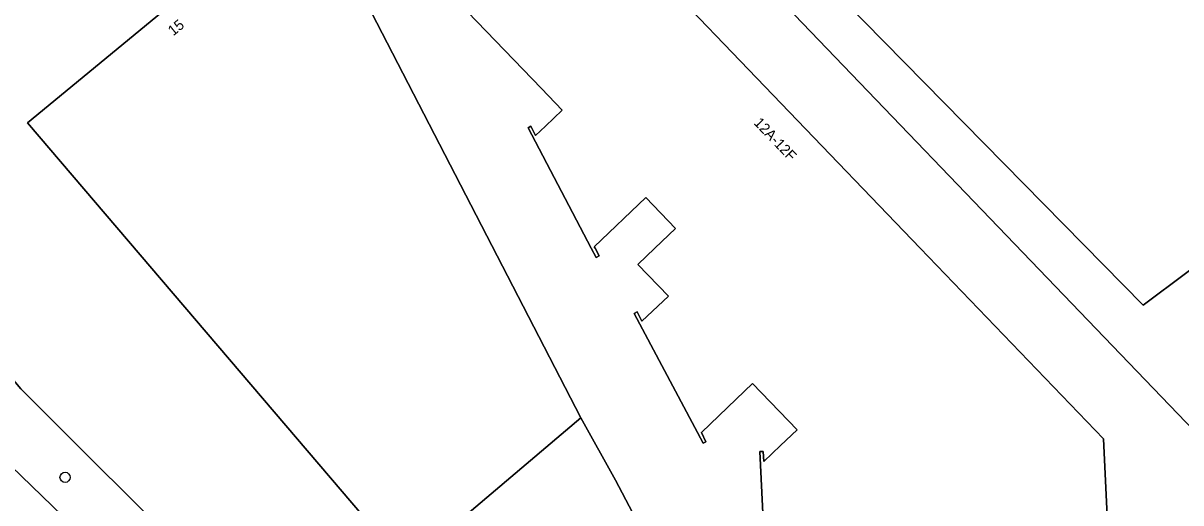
# Model space of a CAD drawing. Extents: x 156141 to 158132, y 385651 to 388333.
# Drawn here: x 156991.8 to 157103, y 387225.5 to 387271.6 of the extents above; entities that cross this region are included whole.
import ezdxf

# ---------------------------------------------------------------- set-up
doc = ezdxf.new("R2010")
doc.units = 0
for name, color, linetype in [('IMGEO_Boom', 7, 'Continuous'), ('IMGEO_Erf', 7, 'Continuous'), ('IMGEO_Groenvoorziening', 7, 'Continuous'), ('IMGEO_Hek', 7, 'Continuous'), ('IMGEO_Pand', 7, 'Continuous'), ('IMGEO_Pand_nummerreeks', 7, 'Continuous'), ('IMGEO_Rijbaan_lokaal_gesloten', 7, 'Continuous')]:
    doc.layers.add(name, color=color, linetype=linetype)

msp = doc.modelspace()

# ---------------------------------------------------------------- linework, layer by layer
at = {"layer": 'IMGEO_Boom'}
msp.add_circle((156995.85, 387227.99), 0.489, dxfattribs=at)
at = {"layer": 'IMGEO_Erf'}
msp.add_lwpolyline([(157102.2, 387360.43), (157098.81, 387358.08), (157089.23, 387351.22), (157088.07, 387350.39), (157077.06, 387342.51), (157051.09, 387323.03), (157046.61, 387319.67), (157039.23, 387314.13), (157031.44, 387308.36), (157112.91, 387223.48), (157114.58, 387221.74), (157153.67, 387254.54), (157146.2, 387263.46), (157163.98, 387278.11)], close=True, dxfattribs=at)
for points in [[(156997.33, 387280.22), (156972.87, 387258.73), (156991.61, 387236.5), (157008.89, 387219.22), (157018.97, 387209.11), (157019.16, 387208.92), (157017.59, 387207.43), (157020.31, 387201.75), (157031.11, 387190.53), (157034.45, 387193.71), (157034.64, 387193.66), (157037.05, 387195.92), (157039.11, 387193.73), (157036.71, 387191.47), (157050.6, 387176.49), (157048.29, 387174.31), (157048.53, 387174.05), (157052.57, 387169.63), (157055.48, 387172.3), (157057.62, 387174.27), (157112.91, 387223.48), (157031.44, 387308.36)], [(157037.92, 387291.74), (157078, 387250), (157095.58, 387231.69), (157096.19, 387218.9)], [(157024.52, 387224.23), (156992.23, 387262.06), (157019.28, 387284.34), (157045.38, 387233.72), (157048.71, 387227.72), (157055.93, 387214)], [(157150.05, 387282.59), (157128.17, 387266.15), (157127.25, 387265.46), (157103.59, 387247.68), (157099.41, 387244.54), (157068.8, 387275.7)], [(157063.23, 387217.34), (157062.59, 387230.46), (157062.91, 387230.48), (157062.97, 387229.5), (157064.58, 387231.05), (157066.16, 387232.55), (157061.88, 387237.02), (157060.3, 387235.5), (157056.97, 387232.29), (157057.41, 387231.39), (157057.13, 387231.26), (157050.52, 387243.74), (157050.8, 387243.88), (157051.25, 387242.99), (157053.81, 387245.41), (157050.88, 387248.45), (157052.5, 387250), (157054.5, 387251.91), (157051.64, 387254.89), (157046.68, 387250.14), (157046.76, 387250), (157047.15, 387249.26), (157046.87, 387249.11), (157046.4, 387250), (157040.32, 387261.59), (157040.6, 387261.73), (157041.05, 387260.84), (157041.99, 387261.74), (157043.59, 387263.28), (157041.6, 387265.34), (157030.08, 387277.33)]]:
    msp.add_lwpolyline(points, dxfattribs=at)
at = {"layer": 'IMGEO_Groenvoorziening'}
msp.add_lwpolyline([(156967.44, 387257.51), (156967.79, 387257.15), (156971.51, 387253.26), (156972.92, 387254.49), (156976.67, 387250.52), (156975.39, 387249.3), (156973, 387247.06), (156981.1, 387238.79), (156983.28, 387236.56), (156983.14, 387236.42), (156983.74, 387235.75), (156994.61, 387225.24), (156996.7, 387223.24), (156998.44, 387221.51), (156999.17, 387220.75), (157000, 387219.91), (157001.47, 387218.42), (157008.89, 387219.22), (156991.61, 387236.5), (156972.87, 387258.73)], dxfattribs=at)
at = {"layer": 'IMGEO_Hek'}
msp.add_lwpolyline([(157031.44, 387308.36), (157112.91, 387223.48)], dxfattribs=at)
at = {"layer": 'IMGEO_Pand'}
for points in [[(157096.19, 387218.9), (157095.58, 387231.69), (157078, 387250), (157037.92, 387291.74)], [(157068.8, 387275.7), (157099.41, 387244.54), (157103.59, 387247.68), (157127.25, 387265.46), (157128.17, 387266.15), (157150.05, 387282.59)], [(157030.08, 387277.33), (157041.6, 387265.34), (157043.59, 387263.28), (157041.99, 387261.74), (157041.05, 387260.84), (157040.6, 387261.73), (157040.32, 387261.59), (157046.4, 387250), (157046.87, 387249.11), (157047.15, 387249.26), (157046.76, 387250), (157046.68, 387250.14), (157051.64, 387254.89), (157054.5, 387251.91), (157052.5, 387250), (157050.88, 387248.45), (157053.81, 387245.41), (157051.25, 387242.99), (157050.8, 387243.88), (157050.52, 387243.74), (157057.13, 387231.26), (157057.41, 387231.39), (157056.97, 387232.29), (157060.3, 387235.5), (157061.88, 387237.02), (157066.16, 387232.55), (157064.58, 387231.05), (157062.97, 387229.5), (157062.91, 387230.48), (157062.59, 387230.46), (157063.23, 387217.34)]]:
    msp.add_lwpolyline(points, dxfattribs=at)
for points in [[(157019.28, 387284.34), (156992.23, 387262.06), (157024.52, 387224.23), (157024.65, 387224.07), (157028.43, 387219.64), (157028.56, 387219.49), (157028.58, 387219.46), (157045.38, 387233.72)], [(157048.71, 387227.72), (157045.38, 387233.72), (157028.58, 387219.46), (157029.27, 387218.69), (157033.86, 387213.64), (157030.2, 387210.16), (157029.11, 387211.4), (157028.93, 387211.23), (157025.29, 387207.79), (157025.49, 387207.58), (157025.58, 387207.67), (157029.24, 387205.77), (157028.67, 387204.65), (157032.82, 387200.3), (157032.62, 387200.11), (157032.82, 387199.9), (157036.4, 387203.32), (157040.37, 387199.16), (157043.99, 387202.61), (157055.93, 387214)]]:
    msp.add_lwpolyline(points, close=True, dxfattribs=at)
at = {"layer": 'IMGEO_Rijbaan_lokaal_gesloten'}
msp.add_lwpolyline([(157052.39, 387165.37), (157048.51, 387169.64), (157044.62, 387173.91), (157038.4, 387180.54), (157032.17, 387187.17), (157031.24, 387188.16), (157030.53, 387188.89), (157030.67, 387189.04), (157030.39, 387189.32), (157022.11, 387197.9), (157018.72, 387201.37), (157014.65, 387205.4), (157014.51, 387205.53), (157014.33, 387205.46), (157013.15, 387206.55), (157001.47, 387218.42), (157000, 387219.91), (156999.17, 387220.75), (156998.44, 387221.51), (156996.7, 387223.24), (156994.61, 387225.24), (156983.74, 387235.75)], dxfattribs=at)

# ---------------------------------------------------------------- texts
at = {"layer": 'IMGEO_Pand_nummerreeks'}
for s, rotation, p in [('15', 39.2705, (157006.24, 387270.36)), ('12A-12F', 313.8364, (157061.94, 387261.99))]:
    msp.add_text(s, height=1, rotation=rotation, dxfattribs=at).set_placement(p)

doc.saveas('drawing.dxf')
